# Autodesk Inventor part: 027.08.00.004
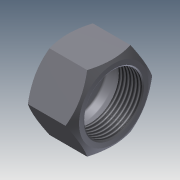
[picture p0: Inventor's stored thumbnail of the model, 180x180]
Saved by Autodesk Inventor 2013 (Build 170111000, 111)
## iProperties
Shininess: 25.0
Length Units: 11269
Angle Units: 11279
Time Units: 11290
Mass Units: 11283
Length Display Precision: 3
Angle Display Precision: 2
Created: 2001-08
Part Number: 027.08.00.004
Document SubType Name: Modeling
Designer: SOleg
Material: Steel, Mild
Density: 7.86 g/cm^3
Density: 0.0
Volumn: 0.0
Area: 0.0
PropertySet Name: Model Information
Control State: 0
Master: False
Checked Out: True
Checked Out Date: 2008-10-15
Last Check In Date: 2008-10-15
Author: SOleg
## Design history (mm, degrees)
node "WorkPlane1"
node "WorkPlane2"
node "WorkPlane6"
node "Sketch1"
node "WorkPoint1"
workplane "Work Plane4"
node "WorkPlane4"
workplane "Work Plane6"
node "WorkPlane7"
sketch "Sketch2"
  geometry: L1 (-23.671, 0)-(-11.836, -20.5); L2 (-11.836, 20.5)-(-23.671, 0); L3 (11.836, 20.5)-(-11.836, 20.5); L4 (23.671, 0)-(11.836, 20.5); L5 (11.836, -20.5)-(23.671, 0); L6 (-11.836, -20.5)-(11.836, -20.5); L7 (0, 0)-(-1, 0)
  constraints: 14 end point, 3 parallel
  dimensions: "d4" = 60 deg angle of L7 L5; "d6" = 41 distance of L5.start L3.start (computed from mdtd1); "d8" = 41 distance of L4.start L2.start (computed from mdtd1); "d10" = 23.67136 distance of L4.start L3.start (computed from mdtd1); "d12" = 23.67136 distance of L1.start L1.end (computed from mdtd1); "d14" = 120 deg angle of L4 L5; "d16" = 120 deg angle of L3 L4; "d18" = 20.5 distance from line of L6 L7.start (computed from mdtd1); "d20" = 23.67136 distance of L4.start L7.start (computed from mdtd1)
extrude "ExtrusionBlind1" new body sketch "Sketch2" distance "d21" = 26 (computed from mdtd10); taper "d22" = 0 deg
node "WorkPlane3"
sketch "Sketch3"
  geometry: L1 (0, 23.671)-(-2.697, 23.671); L2 (0, 23.671)-(0, 19); L3 (-2.697, 23.671)-(0, 19); L4 (-26, 23.671)-(0, 23.671); L5 (0, 0)-(0, 19); L6 (0, 0)-(2, 0); L7 (0, 0)-(2, 0)
  constraints: 14 end point, 3 point on line, 1 horizontal
  dimensions: "d26" = 0 horizontal distance of L5.start L4.end; "d28" = 60 deg angle of L3 L6
revolve "RevolutionAngle1" sketch "Sketch3" stored, may be unused: angle "d29" = 360 deg
sketch "Sketch4"
  geometry: L1 (0, 23.671)-(2.697, 23.671); L2 (0, 23.671)-(0, 19); L3 (2.697, 23.671)-(0, 19); L4 (0, 23.671)-(2.697, 23.671); L5 (0, 0)-(0, 23.671); L6 (0, 0)-(0, 19); L7 (0, 0)-(2, 0); L8 (0, 0)-(2, 0)
  constraints: 16 end point, 3 point on line, 1 horizontal
  dimensions: "d31" = 0 horizontal distance of L5.start L5.end; "d33" = 60 deg angle of L7 L3; "d35" = 19 distance of L6.end L5.start
revolve "RevolutionAngle2" sketch "Sketch4" stored, may be unused: angle "d36" = 360 deg
sketch "Sketch5"
  geometry: L1 (161.449, 165.748)-(161.449, 163.494); L2 (165.971, 166.748)-(162.449, 166.748); L3 (169.449, 165.548)-(166.69, 166.614); L4 (182.449, 166.248)-(182.045, 165.548); L5 (182.449, 149.748)-(182.449, 166.248); L6 (161.449, 149.748)-(182.449, 149.748); L7 (161.449, 163.494)-(161.449, 149.748); L8 (182.449, 149.748)-(182.449, 150.76); L9 (161.449, 149.748)-(182.449, 149.748); L10 (156.449, 168.748)-(156.449, 130.748) reference; L11 (156.449, 149.748)-(198.122, 149.748); L12 (169.449, 165.548)-(182.045, 165.548); A1 r 1 centre (162.449, 165.748) between (162.449, 166.748) and (161.449, 165.748); A2 r 1.993 centre (165.971, 164.754) between (166.69, 166.614) and (165.971, 166.748)
  constraints: 22 end point, 4 point on circle, 4 tangent, 3 vertical, 2 centre point, 2 collinear, 2 parallel, 1 midpoint, 1 point on line
  dimensions: "d38" = 1 radius of A1; "d40" = 13 horizontal distance of L4.start L3.start (computed from mdtd30); "d42" = 21 horizontal distance of L1.start L5.start (computed from mdtd30); "d44" = 30 deg angle of L4 L5; "d46" = 90 deg angle of L6 L7; "d48" = 17 vertical distance of L2.end L6.start; "d50" = 5.24102 horizontal distance of L3.end L1.end; "d52" = 16.5 distance of L4.start L5.start (= 0.1 x mdtd36); "d54" = 13.74582 distance of L1.end L6.start (computed from mdtd36, mdtd38); "d68" = 15.8 distance between parallel lines of L6 L12
revolve "RevolutionAngle3" sketch "Sketch5" stored, may be unused: angle "d57" = 360 deg
node "WorkAxis1"
extrude "ExtrusionBlind2" cut distance "d60" = 8.22323 (computed from mdtd49); taper "d61" = 0 deg
  node "Sketch6" dims "d59" = 26
node "WorkPlane5"
thread "Thread3" dims "d69" = 10, "d70" = 0
body "Solid1"
other parameters: "mdtd36" = 165 [user parameter; used in 2 equation terms], "mdtd38" = 12.2687 [user parameter; used in 1 equation term], "mdtd49" = 82.23227 [user parameter; used in 2 equation terms], "d0" = 0, "d1" = -26 (computed from mdtd10), "d2" = -8.22323 (computed from mdtd49), "d3" = 60 deg (derived), "d5" = 41 (derived), "d7" = 41 (derived), "d9" = 23.67136 (derived), "d11" = 23.67136 (derived), "d13" = 120 deg (derived), "d15" = 120 deg (derived), "d17" = 20.5 (derived), "d19" = 23.67136 (derived), "d23" = 0, "d24" = 0, "d25" = 0 (derived), "d27" = 60 deg (derived), "d30" = 0 (derived), "d32" = 60 deg (derived), "d34" = 19 (derived), "d37" = 1 (derived), "d39" = 13 (derived), "d41" = 21 (derived), "d43" = 30 deg (derived), "d45" = 90 deg (derived), "d47" = 17 (derived), "d49" = 5.24102 (derived), "d51" = 16.5 (derived), "d53" = 13.74582 (derived), "d55" = 150 deg (derived), "d58" = 26 (derived), "d62" = 0, "d63" = 0
